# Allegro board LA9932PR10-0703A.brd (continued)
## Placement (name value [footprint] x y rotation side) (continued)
JCAM1  -  [E-T_3702K-Q08C-07L_8P]  228.21 160.88 0 bottom
JCPU1  -  [LOTES_AZIF0012-P002B_947P-T]  144.94 75.73 180 bottom
JDEG2  -  [HB_A531015-SCHR21_10P]  239.21 72.67 90 top
JDIMM1  -  [TYCO_2-2013290-1_204P]  91.44 35.35 180 bottom
JDIMM2  -  [TYCO_2-2013311-1_204P]  91.44 22.15 180 bottom
JDOCK1  -  [JAE_WD2F144WB1R300_144P]  117.84 161.25 0 bottom
JEXP1  -  [E-T_1001K-F30C-03L_30P-T]  229.69 30.09 270 top
JFAN1  -  [ACES_50273-0040N-001_4P]  47.66 89.43 0 bottom
JHDMI1  -  [CONCR_099ATAC19NBLCNF_19P]  14.44 212 0 bottom
JHP1  -  [SINGA_2SJ3082-000111F_6P-T]  290.99 165.4 270 top
JIO1  -  [E-T_1000K-Y40E-02L_40P]  1.92 176.69 270 bottom
JKB1  -  [HB_A091020-SAHR22_10P]  202.59 101 180 top
JLED1  -  [HB_A520620-SCHR22_6P]  256.17 153.79 180 top
JLOM1  -  [J-L_TNBNRBC80002008_13P-T]  250.25 207.6 0 bottom
JLVDS1  -  [ACES_59003-04006-001_40P]  221.54 170.08 0 bottom
JMDIA1  -  [HB_A520620-SCHR22_6P]  8.55 140.01 180 top
JMINI1  -  [BELLW_80003-8041_52P]  257.96 202.35 0 bottom
JMINI2  -  [BELLW_80003-8041_52P]  193.83 160.09 352.2 bottom
JMINI3  -  [BELLW_80003-1121_52P]  285.79 185.75 270 bottom
JRTC1  -  [ACES_50273-0020N-001_2P]  242.01 154.12 0 bottom
JSATA1  -  [SANTA_196003-1_22P]  81.64 61.8 90 bottom
JSATA2  -  [TYCO_2-2129116-3_31P-T]  164.01 29.82 270 bottom
JSD1  -  [ALPS_SCDACA0101_19P]  215.53 28.45 0 top
JSF1  -  [HB_A090620-SAHR21_6P]  232.34 111.2 90 top
JSIM1  -  [T-SOL_159-1000302602_10P-T]  224.09 157.48 180 top
JSPI1  -  [TYCO_2-2041070-0_20P-T]  212.06 138.5 90 top
JSPK1  -  [ACES_50273-0040N-001_4P]  179.29 9.27 0 bottom
JTAG1  -  [SHORTPADS]  198.31 86.73 0 top
JTCH1  -  [ACES_50228-0067N-001_6P]  181.56 145.11 90 bottom
JTP1  -  [HB_A520820-SCHR22_8P]  188.04 108.27 270 top
JUSB1  -  [SANTA_373130-1_9P]  281.44 207.56 0 bottom
JUSB2  -  [LOTES_ABA-USB-116-P04_9P]  291.52 191.75 90 top
JUSB3  -  [LOTES_ABA-USB-116-P04_9P]  291.52 172.75 90 top
JUSH1  -  [HB_A522020-SCHR22_20P]  40.27 94.81 0 top
JXDP1  -  [MOLEX_52435-2671_26P-T]  94.5 72.23 90 bottom
JXDP2  -  [SAMTE_BSH-030-01-L-D-A_60P]  211.88 110.38 270 bottom
L1  -  [MURAT_DLW21SN900HQ2L_0805_4P]  24.3 205.14 90 top
L2  -  [MURAT_DLW21SN900HQ2L_0805_4P]  13.64 205.14 90 top
L3  -  [MURAT_DLW21SN900HQ2L_0805_4P]  17.19 205.14 90 top
L4  -  [MURAT_DLW21SN900HQ2L_0805_4P]  20.75 205.14 90 top
L10  -  [MURAT_DLW21SN121SQ2L_4P]  230.14 165.71 270 bottom
L11  -  [MURAT_DLW21SN900SQ2L_0805_4P]  190.53 137.13 90 bottom
L13  -  [MURAT_BLM15BB221SN1D_2P]  265.52 159.71 270 top
L29  -  [TAIYO_CBC2012T4R7M_2P]  246.94 168.46 180 top
L45  -  [MURAT_BLM15BD601SN1D_2P]  179.06 24.51 270 top
L47  -  [MURAT_BLM15BD601SN1D_2P]  190.5 31.71 90 top
L51  -  [MURAT_DLW21SN900SQ2L_0805_4P]  274.87 186.78 90 top
L77  -  [MURAT_BLM15PX600SN1D_2P]  283.21 161.38 90 top
L95  -  [MURAT_DLW21SN900HQ2L_0805_4P]  277.98 187.99 90 top
L96  -  [MURAT_DLW21SN900HQ2L_0805_4P]  279.95 188.31 90 top
L99  -  [MURAT_DLW21SN900HQ2L_0805_4P]  136.76 164.11 90 top
L107  -  [MURAT_DLW21SN900SQ2L_0805_4P]  282.23 183.43 45 top
L108  -  [MURAT_DLW21SN900HQ2L_0805_4P]  285.41 188.88 90 top
L109  -  [MURAT_DLW21SN900HQ2L_0805_4P]  287.32 191.18 90 top
L110  -  [MURAT_DLW21SN900SQ2L_0805_4P]  280.65 175.78 0 top
L111  -  [MURAT_DLW21SN900HQ2L_0805_4P]  281.79 173.81 0 top
L112  -  [MURAT_DLW21SN900HQ2L_0805_4P]  281.79 171.78 0 top
L702  -  [MURAT_BLM18PG330SN1D_2P]  178.65 13.11 270 top
L703  -  [MURAT_BLM18PG330SN1D_2P]  180.13 13.11 270 top
L704  -  [MURAT_BLM18PG330SN1D_2P]  182.3 13.12 270 top
L705  -  [MURAT_BLM18PG330SN1D_2P]  183.75 13.12 270 top
L706  -  [MURAT_BLM15BD601SN1D_2P]  283.4 150.33 0 bottom
L707  -  [MURAT_BLM15BD601SN1D_2P]  283.14 159.57 0 top
LE2  -  [MURAT_DLW21SN900HQ2L_0805_4P]  191.75 13.03 0 top
LE4  -  [MURAT_DLW21SN900HQ2L_0805_4P]  191.75 15.19 0 top
LE5  -  [MURAT_DLW21SN900HQ2L_0805_4P]  194.89 31.07 0 top
LED1  -  [LED_LTW-193ZDS5_2P]  277.14 200.7 270 top
LH1  -  [MURAT_BLM18PG181SN1D_2P]  169.05 151.3 0 top
LV16  -  [R_0402]  70.92 148.33 0 top
LV17  -  [R_0402]  58.13 130.03 180 top
LV18  -  [R_0402]  57.22 128.25 90 top
LV19  -  [R_0402]  77.48 141.47 180 top
LV21  -  [R_0402]  58.56 126.74 180 top
LV30  -  [R_0402]  64.12 142.99 0 top
ME1  -  [SHORTPADS]  180.41 129.91 180 top
NOREF  -  []  167.59 15.85 0 top
NOREF#2  -  []  119.48 47.33 0 top
NOREF#3  -  []  3.89 193.15 0 top
NOREF#4  -  []  90.19 137.15 0 top
NOREF#5  -  []  183.39 167.72 0 top
NOREF#6  -  []  250.59 86.75 0 top
NOREF#7  -  []  94.24 42.28 0 top
NOREF#8  -  []  3.89 169.85 0 top
NOREF#9  -  []  257.71 161.85 0 top
NOREF#10  -  []  142.18 118.1 90 top
NOREF#11  -  []  293.49 208.3 0 top
NOREF#12  -  []  115.19 41.83 0 top
NOREF#13  -  []  16.45 270.94 0 top
NOREF#14  -  []  49.34 146.2 0 top
NOREF#15  -  []  227.79 44.15 0 top
NOREF#16  -  []  165.36 -33.98 0 top
NOREF#17  -  []  152.65 76 0 top
NOREF#18  -  []  152.65 105.7 0 top
NOREF#19  -  []  102.15 76 0 top
NOREF#20  -  []  234.59 150.85 0 top
NOREF#21  -  []  102.15 105.7 0 top
NOREF#22  -  []  227.79 23.15 0 top
NOREF#23  -  []  59.79 117.05 0 top
NOREF#24  -  []  89.79 167.72 0 top
NOREF#25  -  []  226.25 60.63 180 bottom
NOREF#26  -  []  216.06 22.88 180 bottom
NOREF#27  -  []  44.03 50.04 180 bottom
NOREF#28  -  []  217.81 18.08 180 bottom
PBATT1  -  [OCTEK_BTJ-09WKFB_9P]  60.79 169.75 0 bottom
PC3  -  [C_0603]  241.37 152.07 0 top
PC5  -  [C_0402]  80.89 166.8 0 top
PC8  -  [C_0805]  10.03 175.97 270 top
PC12  -  [C_0603]  22.54 178.55 0 bottom
PC13  -  [C_0805]  9.91 171.15 270 top
PC14  -  [C_0603]  9.97 172.28 270 bottom
PC17  -  [C_0402]  166.96 167.5 180 top
PC101  -  [C_APXK6R3ARA221MF451]  219.58 46.69 270 top
PC102  -  [C_APXK6R3ARA221MF451]  214.01 55.5 180 top
PC103  -  [C_0402]  205.45 51.41 0 top
PC105  -  [C_0402]  203.27 37.4 270 top
PC106  -  [C_0402]  201.35 48.17 270 top
PC109  -  [C_0805]  202.66 48.59 270 top
PC110  -  [C_0805]  205.04 40.07 270 top
PC111  -  [C_0603]  198.31 43.11 270 top
PC112  -  [C_0603]  198.4 34.41 270 top
PC114  -  [C_0603]  193.3 38.09 0 top
PC116  -  [C_0603]  208.03 33.14 180 top
PC117  -  [C_0603]  202.19 37.33 270 top
PC118  -  [C_0603]  202.19 38.34 90 top
PC119  -  [C_0603]  207.35 42.65 180 top
PC120  -  [C_0603]  194.96 42.23 180 top
PC201  -  [C_APXK2R5ARA331MF451]  160.21 75.3 180 bottom
PC202  -  [C_0805]  169.99 87.39 270 top
PC203  -  [C_0805]  168.15 87.39 270 top
PC205  -  [C_0402]  166.37 92.99 90 top
PC206  -  [C_0603]  174.25 89.84 180 top
PC207  -  [C_0805]  172.68 82.03 180 top
PC208  -  [C_0805]  172.68 83.75 180 top
PC209  -  [C_0402]  177.23 83.25 270 top
PC210  -  [C_0603]  180.53 90.99 0 top
PC211  -  [C_0402]  180.28 83.12 270 top
PC212  -  [C_0603]  161.1 80.83 0 top
PC213  -  [C_0603]  178.25 89.72 90 top
PC214  -  [C_0402]  178.5 82.21 90 top
PC215  -  [C_0402]  180.52 86.67 0 top
PC216  -  [C_SX]  154.18 82.14 90 bottom
PC301  -  [C_APXK2R5ARA331MF451]  158.75 102.99 180 bottom
PC302  -  [C_0402]  169.76 96.94 90 top
PC303  -  [C_0402]  167.32 94.81 270 top
PC304  -  [C_0805]  168.47 96.93 90 top
PC305  -  [C_0805]  166.75 96.93 90 top
PC306  -  [C_0603]  172.47 95.49 270 top
PC307  -  [C_0402]  179.31 95.75 0 top
PC308  -  [C_0603]  173.93 98.48 0 top
PC309  -  [C_0603]  162.18 100.96 90 top
PC310  -  [C_0805]  163.6 105.45 0 top
PC400  -  [C_0603]  203.2 58.54 180 top
PC401  -  [C_0402]  203.15 57.46 180 top
PC402  -  [C_0402]  205.37 55.11 180 top
PC403  -  [C_0603]  194.88 59.74 180 top
PC404  -  [C_0603]  194.88 58.47 180 top
PC405  -  [C_0402]  194.71 60.82 180 top
PC406  -  [C_0402]  200.22 52.9 270 top
PC407  -  [C_0402]  198.82 58.33 90 top
PC500  -  [C_0402]  124.72 148.59 270 bottom
PC509  -  [C_0603]  124.4 138.17 90 bottom
PC510  -  [C_0402]  126.57 149.47 180 bottom
PC511  -  [C_0603]  128.02 139.56 270 bottom
PC512  -  [C_0805]  117.77 135.94 0 top
PC513  -  [C_0805]  117.77 135.94 0 bottom
PC514  -  [C_0805]  117.77 137.72 0 bottom
PC515  -  [C_0402]  118.04 139.06 0 bottom
PC516  -  [C_0402]  98.87 152.91 270 bottom
PC518  -  [C_0402]  127.61 140.92 180 top
PC520  -  [C_0402]  129.8 145.9 90 top
PC521  -  [C_0402]  131.95 143.61 90 bottom
PC522  -  [C_0603]  119.57 141.53 0 bottom
PC524  -  [C_0603]  115 129.28 0 top
PC525  -  [C_0402]  125.99 144.95 90 top
PC526  -  [C_0402]  125.1 144.95 90 top
PC527  -  [C_0402]  126.87 144.95 90 top
PC528  -  [C_0402]  129.16 142.56 270 bottom
PC529  -  [C_0603]  132.4 141.47 180 bottom
PC530  -  [C_EEEFK1E101YP]  115.24 144.07 90 bottom
PC531  -  [C_EEEFK1E101YP]  108.13 144.03 90 bottom
PC532  -  [C_EEEFK1E101YP]  100.89 144.03 90 bottom
PC533  -  [C_0805]  129.19 134.29 180 top
PC534  -  [C_0805]  129.19 132.58 180 bottom
PC535  -  [C_0805]  129.19 134.29 180 bottom
PC536  -  [C_0402]  128.92 135.63 180 bottom
PC538  -  [C_0603]  132.4 140.26 180 bottom
PC539  -  [C_0402]  130.06 143.63 180 bottom
PC540  -  [C_0402]  130.06 144.52 180 bottom
PC541  -  [C_0402]  126.23 143.69 0 top
PC542  -  [C_0603]  125.6 138.17 90 bottom
PC543  -  [C_0603]  128.84 128.26 180 top
PC545  -  [C_0402]  129.29 143.64 270 top
PC546  -  [C_0402]  126.23 142.8 0 top
PC547  -  [C_0402]  128.67 145.02 180 top
PC548  -  [C_0402]  119.25 145.27 90 bottom
PC600  -  [C_0402]  17.12 143.8 90 top
PC601  -  [C_0603]  13.15 157.03 90 top
PC602  -  [C_0402]  4.5 162.17 0 bottom
PC603  -  [C_0805]  14.67 156.94 90 top
PC604  -  [C_0805]  14.67 156.94 90 bottom
PC605  -  [C_0603]  20.96 154.49 270 top
PC606  -  [C_D2]  50.14 153.91 0 top
PC607  -  [C_0603]  9.78 164.84 180 bottom
PC608  -  [C_0603]  24.39 154.87 270 top
PC610  -  [C_0603]  22.23 154.87 270 top
PC611  -  [C_0402]  24.13 144.15 270 top
PC612  -  [C_0402]  25.91 140.57 90 top
PC613  -  [C_0402]  24.14 142.36 180 top
PC614  -  [C_0402]  25.02 143.26 270 top
PC615  -  [C_0402]  25.91 144.15 270 top
PC616  -  [C_0402]  26.86 144.15 270 top
PC617  -  [C_0603]  27.88 149.02 0 top
PC618  -  [C_0603]  27.88 150.23 0 top
PC619  -  [C_0603]  16.51 157.66 0 top
PC621  -  [C_0805]  16.36 156.07 0 top
PC622  -  [C_0805]  16.36 156.07 0 bottom
PC623  -  [C_0603]  26.93 153.85 180 top
PC624  -  [C_0402]  27.8 144.77 0 top
PC626  -  [C_0603]  29.78 147.75 270 top
PC627  -  [C_0402]  30.86 147.64 270 top
PC628  -  [C_D2]  38.93 159.53 270 bottom
PC629  -  [C_D2]  51.65 127.82 180 top
PC630  -  [C_0402]  28.72 145.66 180 top
PC631  -  [C_0603]  23.88 156.96 270 bottom
PC632  -  [C_0402]  29.97 145.42 270 top
PC660  -  [C_0603]  104.9 131.63 90 bottom
PC661  -  [C_0603]  104.33 139.69 90 bottom
PC662  -  [C_0603]  104.33 139.69 90 top
PC663  -  [C_0603]  104.33 138.17 270 top
PC664  -  [C_0603]  104.33 138.17 270 bottom
PC665  -  [C_0402]  108.52 133.54 270 top
PC666  -  [C_0402]  108.02 130.79 90 top
PC667  -  [C_0402]  104.92 135.12 180 bottom
PC668  -  [C_0402]  107.24 128.32 0 bottom
PC669  -  [C_0603]  106.94 123.88 270 bottom
PC670  -  [C_0603]  108.14 123.88 270 bottom
PC672  -  [C_0603]  99.06 128.26 0 bottom
PC674  -  [C_0402]  99.24 129.34 0 bottom
PC675  -  [C_0402]  106.16 121.47 0 bottom
PC677  -  [C_D2]  49.81 132.64 180 top
PC680  -  [C_0603]  103.7 131.63 90 bottom
PC700  -  [C_0603]  25.6 170.09 0 top
PC703  -  [C_0603]  51.88 164.57 90 bottom
PC704  -  [C_0402]  52.31 166.87 0 top
PC705  -  [C_0402]  52.96 165.42 270 bottom
PC706  -  [C_0603]  56.01 160.65 0 top
PC707  -  [C_0805]  55.18 166.21 90 top
PC708  -  [C_0402]  50.43 163.82 180 bottom
PC709  -  [C_0603]  56.77 164.96 180 top
PC710  -  [C_0402]  57.35 159.44 180 bottom
PC712  -  [C_0805]  64.26 152.64 180 bottom
PC713  -  [C_0805]  64.26 154.36 180 bottom
PC714  -  [C_0805]  58.13 158.04 180 bottom
PC715  -  [C_0603]  67.06 154.3 180 top
PC716  -  [C_0402]  50.43 162.93 180 bottom
PC717  -  [C_0603]  87.34 154.12 270 bottom
PC718  -  [C_0805]  88.84 154.26 270 bottom
PC719  -  [C_0805]  90.62 154.26 270 bottom
PC720  -  [C_0603]  45.47 168.58 270 bottom
PC721  -  [C_0402]  51.75 159.96 270 bottom
PC722  -  [C_0402]  51.77 158.11 180 bottom
PC723  -  [C_0402]  50.87 159.04 90 bottom
PC724  -  [C_0805]  59.88 167.21 270 top
PC725  -  [C_0402]  221.44 141.15 180 top
PC726  -  [C_0402]  229.81 140.4 270 top
PC727  -  [C_0402]  231.99 145.11 180 top
PC728  -  [C_0805]  61.6 167.21 270 top
PC729  -  [C_0402]  223.08 147.36 90 top
PC730  -  [C_0402]  221.5 145.79 180 top
PC731  -  [C_0805]  81.89 154.46 270 bottom
PC732  -  [C_0805]  83.67 154.46 270 bottom
PC733  -  [C_0402]  232.65 138.1 0 top
PC734  -  [C_0805]  58.13 156.33 180 bottom
PC735  -  [C_0603]  63.27 152.31 180 top
PC736  -  [C_0402]  230.9 141.56 270 top
PC737  -  [C_0805]  83.28 163.6 180 top
PC738  -  [C_0805]  83.28 161.79 180 top
PC739  -  [C_0805]  83.28 165.38 180 top
PC801  -  [C_0402]  233.49 82.91 90 top
PC805  -  [C_0402]  227.98 87.75 180 top
PC807  -  [C_0805]  99.51 169.83 90 top
PC808  -  [C_0402]  193.11 46.36 270 top
PC809  -  [C_0402]  101.79 163.52 270 top
PC810  -  [C_0402]  192.09 46.36 270 top
PC811  -  [C_0603]  72.65 152.29 270 top
PC812  -  [C_0402]  184.85 45.57 90 top
PC813  -  [C_0603]  35.56 138.99 270 top
PC814  -  [C_0402]  176 16.96 90 top
PC815  -  [C_0603]  37.21 137.15 270 top
PC816  -  [C_0603]  43.82 137.47 270 top
PC817  -  [C_0402]  44.9 137.54 270 top
PC818  -  [C_0603]  41.72 137.18 270 top
PC819  -  [C_0603]  46.04 140.13 270 top
PC820  -  [C_0603]  35.5 140.13 180 top
PC900  -  [C_0805]  118.05 97.55 270 bottom
PC901  -  [C_0805]  119.95 97.55 270 bottom
PC902  -  [C_0805]  121.86 97.55 270 bottom
PC903  -  [C_0805]  123.76 97.55 270 bottom
PC904  -  [C_0805]  125.67 97.55 270 bottom
PC905  -  [C_D1]  130.61 116.2 0 bottom
PC906  -  [C_D1]  120.39 120.32 0 bottom
PC907  -  [C_D1]  124.58 92.76 0 top
PC908  -  [C_D1]  126.36 120.32 0 top
PC909  -  [C_0805]  127.57 97.55 270 bottom
PC910  -  [C_0805]  129.48 97.55 270 bottom
PC911  -  [C_0805]  131.38 97.55 270 bottom
PC912  -  [C_0805]  133.29 97.55 270 bottom
PC913  -  [C_0805]  135.19 97.55 270 bottom
PC914  -  [C_0805]  137.1 97.55 270 bottom
PC916  -  [C_D1]  120.47 120.2 180 top
PC917  -  [C_0805]  116.84 114.65 90 bottom
PC918  -  [C_0805]  120.46 114.65 90 bottom
PC919  -  [C_0805]  123.83 114.65 90 bottom
PC920  -  [C_0805]  127.51 114.65 90 bottom
PC921  -  [C_0805]  118.05 97.55 270 top
PC922  -  [C_0805]  137.1 97.55 270 top
PC923  -  [C_0805]  135.19 97.55 270 top
PC924  -  [C_0805]  133.29 97.55 270 top
PC925  -  [C_0805]  131.38 97.55 270 top
PC926  -  [C_0805]  129.48 97.55 270 top
PC927  -  [C_0402]  68 135.44 0 top
PC928  -  [C_0402]  71.87 133.98 0 top
PC929  -  [C_0402]  70.94 132.81 180 top
PC930  -  [C_0402]  73.78 135.44 0 top
PC931  -  [C_0402]  68.91 132.83 180 top
PC932  -  [C_0402]  68 131.63 0 top
PC933  -  [C_0402]  68 133.98 0 top
PC934  -  [C_0402]  71.87 135.44 0 top
PC935  -  [C_0805]  127.57 97.55 270 top
PC936  -  [C_0805]  125.67 97.55 270 top
PC937  -  [C_0805]  123.76 97.55 270 top
PC938  -  [C_0805]  121.86 97.55 270 top
PC939  -  [C_0805]  119.95 97.55 270 top
PC940  -  [C_0805]  127.51 114.65 90 top
PC941  -  [C_0805]  123.83 114.65 90 top
PC942  -  [C_0805]  120.46 114.65 90 top
PC943  -  [C_0805]  116.84 114.65 90 top
PC944  -  [C_0402]  73.84 133.98 0 top
PC945  -  [C_0402]  71.81 131.63 0 top
PC946  -  [C_0402]  69.97 133.98 0 top
PC947  -  [C_0402]  72.79 132.81 180 top
PC948  -  [C_0402]  73.84 131.63 0 top
PC949  -  [C_0402]  74.75 132.83 180 top
PC950  -  [C_0402]  70.03 131.63 0 top
PC951  -  [C_0402]  74.69 136.58 180 top
PC963  -  [C_0805]  56.22 139.75 180 bottom
PC964  -  [C_0805]  56.22 138.04 180 bottom
PC965  -  [C_0805]  56.22 141.47 180 bottom
PC966  -  [C_0805]  56.22 143.18 180 bottom
PC970  -  [C_0805]  56.22 144.9 180 bottom
PC971  -  [C_0805]  56.22 146.61 180 bottom
PC972  -  [C_0805]  56.22 148.33 180 bottom
PD2  -  [TVNST52302AB0_SOT523-3]  74.58 165.81 270 top
PD3  -  [BAS40-05W_SC70-3]  240.41 152.67 180 top
PD4  -  [TVNST52302AB0_SOT523-3]  71.87 165.81 270 top
PD7  -  [SDMK0340L-7-F_SOD323-2]  166.44 163.87 0 top
PD700  -  [SBR3A40SA-13_SMA2]  22.13 170.81 180 top
PD701  -  [RB717F_SOT323-3]  46.16 167.38 90 top
PD702  -  [RB751V-40_SOD323-2]  57.84 162.17 180 top
PD800  -  [PDS5100H-13_POWERDI5-3]  95.06 159.88 180 top
PD806  -  [PDS5100H-13_POWERDI5-3]  85.11 158.57 180 top
PD807  -  [SDMK0340L-7-F_SOD323-2]  171.52 75.94 90 top
PD808  -  [PDS5100H-13_POWERDI5-3]  103.06 165.53 0 bottom
PD810  -  [RB717F_SOT323-3]  186.19 47.87 270 top
PD811  -  [SDMK0340L-7-F_SOD323-2]  111.44 156.14 90 top
PD813  -  [RB717F_SOT323-3]  179.9 39.42 270 top
PD815  -  [RB717F_SOT323-3]  171.78 22 270 top
PD818  -  [SDMK0340L-7-F_SOD323-2]  225.94 75.49 0 top
PD819  -  [SDMK0340L-7-F_SOD323-2]  186.25 50.3 90 top
PD820  -  [SDMK0340L-7-F_SOD323-2]  175.2 22.26 90 top
PD821  -  [SDMK0340L-7-F_SOD323-2]  179.81 16.87 180 top
PH500  -  [R_0402]  135.83 133.23 270 bottom
PH501  -  [R_0402]  136.72 123.95 270 bottom
PH600  -  [R_0402]  14.1 160.72 270 bottom
PH601  -  [R_0402]  28.84 155.63 180 bottom
PJP1  -  [JUMP_43X118]  24.58 182.38 90 bottom
PJP2  -  [JUMP_43X39]  25.73 201.67 180 top
PJP3  -  [JUMP_43X79]  80.54 39.74 0 top
PJP4  -  [JUMP_43X79]  174.2 48.25 0 top
PJP53  -  [JUMP_43X39]  89.92 55.12 270 top
PJP60  -  [JUMP_43X79]  264.63 157.28 0 bottom
PJP61  -  [JUMP_43X39]  209.68 119.51 270 top
PJP62  -  [JUMP_43X39]  274.63 156.07 180 bottom
PJP63  -  [JUMP_43X39]  183.45 78.78 90 top
PJP64  -  [JUMP_43X39]  78.73 46.66 0 top
PJP65  -  [JUMP_43X39]  220.87 68.57 180 top
PJP67  -  [JUMP_43X39]  191.76 167.57 0 top
PJP100  -  [JUMP_43X79]  217.36 51.78 270 top
PJP101  -  [JUMP_43X118]  218.21 61.78 0 top
PJP102  -  [JUMP_43X118]  221.87 50.68 90 top
PJP103  -  [JUMP_43X118]  218.21 56.51 0 top
PJP200  -  [JUMP_43X118]  169.74 90.56 90 top
PJP201  -  [JUMP_43X39]  171.82 85.72 0 top
PJP202  -  [JUMP_43X39]  174.89 82.29 180 top
PJP203  -  [JUMP_43X118]  152.29 57.55 45 top
PJP204  -  [JUMP_43X118]  148.61 61.23 45 top
PJP300  -  [JUMP_43X79]  169.67 94.12 90 top
PJP301  -  [JUMP_43X118]  160.34 105.7 270 top
PJP400  -  [JUMP_43X79]  204.87 57.65 0 top
PJP401  -  [JUMP_43X79]  197.36 62.01 270 top
PJP500  -  [JUMP_43X118]  100.08 156.22 90 bottom
PJP600  -  [JUMP_43X118]  3.96 158.87 0 bottom
PJP602  -  [JUMP_43X39]  28.64 143.32 270 top
PJP609  -  [JUMP_43X79]  103.82 130.02 270 bottom
PJP610  -  [JUMP_43X79]  101.5 139.18 0 bottom
PJP611  -  [JUMP_43X79]  107.51 126.65 270 bottom
PJP612  -  [JUMP_43X79]  95.78 125.78 0 bottom
PJP700  -  [JUMP_43X118]  60.01 163.48 270 bottom
PJP701  -  [JUMP_43X39]  49.21 161.74 270 bottom
PJP702  -  [JUMP_43X79]  295.42 185.14 90 top
PJPDC1  -  [JESS_UCNR2451M005-0_5P]  16.96 178.65 90 bottom
PL2  -  [TAIYO_FBMJ4516HS720NT_2P]  76.53 165.49 270 top
PL3  -  [TAIYO_FBMJ4516HS720NT_2P]  79.02 165.49 270 top
PL4  -  [MURAT_BLM15AG102SN1D_2P]  12.1 182.28 90 bottom
PL5  -  [KC_FBMA-L18-453215_L1812_2P]  11.24 177.91 270 bottom
PL101  -  [CYNTE_PCMB063T-2R2MS_2P]  218.22 36.34 180 top
PL102  -  [CYNTE_PCMB063T-3R3MS_2P]  212 43.32 90 top
PL103  -  [CYNTE_PCMB053T-1R0MS_2P]  198.32 49.79 270 top
PL201  -  [TOKO_FDUE1040D-1R0M-P3_2P]  161.93 81.65 90 bottom
PL301  -  [TOKO_FDSD0630-H-1R0M-P3_2P]  164.66 95.81 180 bottom
PL401  -  [CYNTE_PH041H-1R0MS_2P]  197.7 55.11 180 top
PL502  -  [NEC_MPC0740LR42C_2P]  114.37 121.29 90 bottom
PL503  -  [NEC_MPC0740LR42C_2P]  132.65 121.29 90 bottom
PL504  -  [L_1812-1806]  100.08 154.76 90 bottom
PL600  -  [NEC_MPC0740LR42C_2P]  19.74 166.49 180 bottom
PL601  -  [NEC_MPC0740LR42C_2P]  31.3 159.63 180 bottom
PL602  -  [L_1812-1806]  6.52 158.87 180 bottom
PL603  -  [TOKO_FDSD0420-H-1R0M-P3T_2P]  107.38 136.92 90 bottom
PL700  -  [TOKO_FDVE1040-H-5R6M-P3_2P]  82.18 160.48 180 bottom
PL701  -  [CYNTE_PCMB053T-1R0MS_2P]  60.01 160.88 90 bottom
PQ1  -  [FDV301N_NL_SOT23-3]  216.79 124.03 180 top
PQ2  -  [MMST3904-7-F_SOT323-3]  218.95 119.43 90 top
PQ4  -  [FDS6679AZ_SO8]  15.62 176.37 180 top
PQ6  -  [IMD2AT-108_SC74-6]  9.98 179.25 90 top
PQ7  -  [FDN338P_NL_SOT23-3]  167.45 171.47 180 top
PQ101  -  [SIS412DN-T1-GE3_POWERPAK8-5]  209.65 38.62 90 top
PQ102  -  [SIS412DN-T1-GE3_POWERPAK8-5]  207.11 48.15 90 top
PQ103  -  [SI7716ADN-T1-GE3_POWERPAK8-5]  206.78 36.67 270 top
PQ104  -  [SI7716ADN-T1-GE3_POWERPAK8-5]  204.24 46.19 270 top
PQ201  -  [SIR472DP-T1-GE3_POWERPAK8-5]  160.91 91.73 270 top
PQ203  -  [SIR818DP-T1_POWERPAK-SO8-5]  166.25 82.54 90 top
PQ301  -  [SIS412DN-T1-GE3_POWERPAK8-5]  162.27 95.6 270 top
PQ303  -  [SI7716ADN-T1-GE3_POWERPAK8-5]  165.2 97.49 90 top
PQ505  -  [SIR472DP-T1-GE3_POWERPAK8-5]  116.33 130.48 180 bottom
PQ508  -  [SI7170DP-T1-GE3_POWERPAK8-5]  118.81 130.23 0 bottom
PQ509  -  [SIR472DP-T1-GE3_POWERPAK8-5]  134.43 130.48 180 bottom
PQ512  -  [SI7170DP-T1-GE3_POWERPAK8-5]  124.4 130.23 0 bottom
PQ600  -  [CSD86350Q5D_SON8]  12.05 156.81 180 bottom
PQ601  -  [CSD86350Q5D_SON8]  16.42 158.63 90 bottom
PQ610  -  [SSM3K7002FU_SC70-3]  102.11 119.5 270 bottom
PQ700  -  [SI4835BDY-T1-E3_SO8]  23.03 173.35 90 top
PQ701  -  [NTR4502PT1G_SOT23-3]  37.66 168.67 180 top
PQ702  -  [NTR4502PT1G_SOT23-3]  33.59 168.67 180 top
PQ703  -  [NTGD4161PT1G_TSOP6]  147.42 166.48 270 top
PQ704  -  [SIR472DP-T1-GE3_POWERPAK8-5]  68.9 165.6 270 bottom
PQ705  -  [SIR472DP-T1-GE3_POWERPAK8-5]  68.9 160.01 270 bottom
PQ706  -  [SIR472DP-T1-GE3_POWERPAK8-5]  63.43 159.88 270 top
PQ707  -  [2N7002DW-T-R7_SOT363-6]  234.22 144.15 270 top
PQ709  -  [RHU002N06_SOT323-3]  223.29 138.34 0 top
PQ710  -  [RHU002N06_SOT323-3]  237.36 138.83 0 top
PQ711  -  [SIR472DP-T1-GE3_POWERPAK8-5]  63.43 165.6 270 top
PQ800  -  [SI4835BDY-T1-E3_SO8]  97.47 156.62 180 top
PQ801  -  [FDN338P_NL_SOT23-3]  168.53 76.28 180 top
PQ802  -  [RHU002N06_SOT323-3]  226.25 82.5 0 top
PQ805  -  [2N7002DW-T-R7_SOT363-6]  226.02 78.43 270 top
PQ806  -  [2N7002DW-T-R7_SOT363-6]  230.34 80.97 270 top
PQ807  -  [2N7002DW-T-R7_SOT363-6]  172.87 73.16 270 top
PQ809  -  [SI4835BDY-T1-E3_SO8]  85.51 151.5 90 top
PQ810  -  [FDS6679AZ_SO8]  101.31 168.58 90 bottom
PQ811  -  [FDS6679AZ_SO8]  77.97 158.59 180 top
PQ812  -  [2N7002DW-T-R7_SOT363-6]  112.13 151.85 0 top
PQ813  -  [2N7002DW-T-R7_SOT363-6]  187.1 39.76 270 top
PQ814  -  [FDN338P_NL_SOT23-3]  181.08 36.19 270 top
PQ815  -  [FDS6679AZ_SO8]  106.87 161.95 180 top
PQ816  -  [FDV301N_NL_SOT23-3]  98.87 163.03 0 top
PQ817  -  [RHU002N06_SOT323-3]  188.47 51.78 180 top
PQ818  -  [RHU002N06_SOT323-3]  179.01 45.74 0 top
PQ819  -  [2N7002DW-T-R7_SOT363-6]  182.92 49.19 90 top
PQ821  -  [2N7002DW-T-R7_SOT363-6]  188.82 41.12 90 top
PQ822  -  [FDN338P_NL_SOT23-3]  181.21 42.66 270 top
PQ823  -  [FDN338P_NL_SOT23-3]  214.64 94.29 270 top
PQ824  -  [2N7002DW-T-R7_SOT363-6]  220.52 93.36 0 top
PQ825  -  [RHU002N06_SOT323-3]  194.95 81.63 180 top
PQ826  -  [FDS6679AZ_SO8]  103.47 167.88 270 top
PQ827  -  [RHU002N06_SOT323-3]  184.75 39.42 90 top
PQ828  -  [FDN338P_NL_SOT23-3]  168.15 22.16 0 top
PQ829  -  [RHU002N06_SOT323-3]  170.77 24.67 270 top
PQ830  -  [FDN338P_NL_SOT23-3]  176.15 14.49 90 top
PQ831  -  [RHU002N06_SOT323-3]  174.55 18.89 90 top
PR1  -  [R_0402]  242.13 153.65 90 top
PR6  -  [R_0402]  163.31 161.71 0 top
PR10  -  [R_0402]  219.27 123.89 270 top
PR11  -  [R_0402]  220.14 124.77 0 top
PR12  -  [R_0402]  220.16 122.98 90 top
PR13  -  [R_0402]  214.31 122.85 90 top
PR14  -  [R_0402]  221.18 119.12 180 top
PR15  -  [R_0402]  214.25 121.01 90 top
PR16  -  [R_0402]  220.27 120.07 0 top
PR18  -  [R_0402]  8.7 174.28 90 top
PR20  -  [R_0402]  10.36 172.27 180 top
PR22  -  [R_0805]  11.5 172.42 270 bottom
PR23  -  [R_0402]  7.81 175.2 270 top
PR25  -  [R_0402]  8.71 176.08 180 top
PR26  -  [R0402_0OHM]  168.8 167.5 180 top
PR100  -  [R_0402]  193.79 36.11 0 top
PR101  -  [R_0402]  193.79 39.23 0 top
PR102  -  [R_0402]  193.79 35.17 0 top
PR103  -  [R0402_0OHM]  194.71 37 180 top
PR104  -  [R_0402]  193.79 40.12 0 top
PR105  -  [R_0402]  194.71 34.28 180 top
PR106  -  [R_0402]  194.71 41.01 180 top
PR107  -  [R_0603]  199.53 41.71 90 top
PR108  -  [R_0603]  199.67 33.01 90 top
PR109  -  [R_1206]  204.92 33.2 90 top
PR110  -  [R0402_0OHM]  196.36 42.6 270 top
PR111  -  [R_0402]  197.25 42.6 270 top
PR112  -  [R_1206]  204.6 42.34 180 top
PR118  -  [R0402_0OHM]  196.37 33.51 90 top
PR119  -  [R_0402]  197.26 34.42 270 top
PR200  -  [R_0603]  172.91 88.7 270 top
PR201  -  [R_0402]  176.28 90.62 270 top
PR202  -  [R_1206]  163.7 80.44 0 top
PR203  -  [R_0603]  179.45 91.11 270 top
PR204  -  [R_0402]  179.39 83.12 270 top
PR205  -  [R_0402]  181.37 88.64 180 top
PR206  -  [R_0402]  181.37 87.75 180 top
PR207  -  [R_0402]  181.43 84 180 top
PR208  -  [R0402_0OHM]  181.43 84.89 180 top
PR209  -  [R_0402]  181.37 89.53 180 top
PR210  -  [R0402_0OHM]  181.43 85.78 180 top
PR211  -  [R0402_0OHM]  177.17 90.62 270 top
PR300  -  [R_0402]  178.18 93.09 270 top
PR301  -  [R_0603]  174.44 92.95 180 top
PR302  -  [R_0402]  179.07 92.18 90 top
PR303  -  [R_0402]  180.23 93.97 180 top
PR304  -  [R_1206]  163.64 101.46 0 top
PR305  -  [R_0402]  177.81 98.29 180 top
PR306  -  [R_0402]  180.23 97.53 180 top
PR307  -  [R_0402]  180.23 96.64 180 top
PR308  -  [R0402_0OHM]  180.23 94.86 180 top
PR309  -  [R0402_0OHM]  173.12 96.57 180 top
PR401  -  [R_0805]  200.34 59.26 270 top
PR402  -  [R_0402]  205.37 54.22 180 top
PR403  -  [R_0402]  202 51.98 90 top
PR405  -  [R_0402]  204.46 53.33 0 top
PR406  -  [R0402_0OHM]  201.11 51.98 90 top
PR500  -  [R_0402]  121.03 146.5 180 bottom
PR503  -  [R_0402]  121.03 147.39 180 bottom
PR504  -  [R_0402]  121.03 148.28 180 bottom
PR507  -  [R_0402]  119.88 143.82 0 bottom
PR509  -  [R_0402]  120.12 144.71 0 bottom
PR511  -  [R0402_0OHM]  122.75 148.59 270 bottom
PR512  -  [R_0402]  120.12 145.6 0 bottom
PR519  -  [R_0402]  123.83 147.68 90 bottom
PR520  -  [R0402_0OHM]  123.33 139.56 180 bottom
PR521  -  [R_0402]  125.6 147.68 90 bottom
PR524  -  [R0402_0OHM]  126.49 148.59 270 bottom
PR525  -  [R_0402]  127.38 148.59 270 bottom
PR526  -  [R0402_0OHM]  129.1 139.58 270 bottom
PR528  -  [R_0402]  128.27 148.59 270 bottom
PR529  -  [R_0402]  128.91 146.81 270 bottom
PR530  -  [R_0402]  128.77 141.85 0 top
PR533  -  [R_0402]  128.92 147.69 180 top
PR534  -  [R_0603]  119.57 142.74 0 bottom
PR535  -  [R_0402]  131 144.53 270 bottom
PR536  -  [R_0603]  133.61 138.99 270 bottom
PR537  -  [R_0402]  128.91 145.9 90 top
PR538  -  [R_0603]  133.61 137.59 90 top
PR539  -  [R_0402]  125.08 146.74 0 top
PR541  -  [R_1206]  116.46 130.67 90 top
PR543  -  [R_0402]  128.02 145.9 90 top
PR544  -  [R_0402]  134.69 138.15 90 bottom
PR545  -  [R_0402]  130.99 145.41 0 bottom
PR546  -  [R_0402]  134.69 139.07 270 top
PR548  -  [R0402_0OHM]  130.93 142.55 0 bottom
PR549  -  [R_0402]  130.05 142.56 270 bottom
PR550  -  [R_0603]  126.81 138.17 90 bottom
PR551  -  [R_0402]  130.05 139.87 90 bottom
PR552  -  [R_0603]  132.4 138.99 270 bottom
PR553  -  [R_0603]  132.4 137.59 90 top
PR554  -  [R_1206]  127.89 130.1 90 top
PR555  -  [R_0402]  131.32 139.07 270 top
PR556  -  [R_0402]  131.26 138.09 90 bottom
PR558  -  [R_0402]  127.14 141.89 180 top
PR600  -  [R0402_0OHM]  15.36 144.71 0 top
PR602  -  [R_0402]  18.18 146.83 180 top
PR604  -  [R_0402]  18.18 147.89 180 top
PR605  -  [R_0402]  17.26 148.96 0 top
PR607  -  [R_0402]  15.36 143.82 0 top
PR608  -  [R_0402]  18.18 150.1 180 top
PR610  -  [R_0402]  17.26 151.56 0 top
PR612  -  [R_0402]  17.26 152.45 0 top
PR614  -  [R_0603]  19.75 153.09 90 top
PR615  -  [R_0402]  17.91 145.95 180 top
PR616  -  [R_0402]  18.01 143.8 90 top
PR618  -  [R0402_0OHM]  15.95 148.96 180 top
PR619  -  [R_0402]  33.21 150.62 270 top
PR620  -  [R0402_0OHM]  15.95 147.89 180 top
PR621  -  [R0402_0OHM]  15.95 150.1 180 top
PR622  -  [R_1206]  6.86 164.84 270 bottom
PR623  -  [R_0402]  34.16 150.62 270 top
PR624  -  [R_0402]  35.05 150.62 270 top
PR625  -  [R0402_0OHM]  15.95 151.56 180 top
PR626  -  [R_0402]  36.01 149.71 90 top
PR627  -  [R_0402]  19.81 143.8 90 top
PR628  -  [R0402_0OHM]  15.95 152.45 180 top
PR629  -  [R0402_0OHM]  18.92 143.8 90 top
PR631  -  [R_0402]  21.59 143.33 90 top
PR632  -  [R_0402]  21.6 141.47 180 top
PR633  -  [R_0402]  21.6 140.58 180 top
PR634  -  [R_0402]  20.97 142.42 180 top
PR635  -  [R0402_0OHM]  23.31 153.99 90 top
PR638  -  [R_0402]  23.24 144.15 270 top
PR639  -  [R_0402]  24.12 140.58 0 top
PR640  -  [R_0402]  26.8 140.57 90 top
PR642  -  [R_0402]  25.03 141.47 180 top
PR643  -  [R0402_0OHM]  30.32 150.06 0 top
PR644  -  [R_0402]  23.24 141.48 270 top
PR645  -  [R_0402]  30.32 149.17 0 top
PR648  -  [R_0402]  31.75 147.64 270 top
PR649  -  [R_0603]  27.43 151.31 90 top
PR650  -  [R0402_0OHM]  48.46 135.56 180 top
PR651  -  [R_0402]  30.1 153.61 270 top
PR652  -  [R_0402]  31.05 153.61 270 top
PR653  -  [R_1206]  22.48 156.01 180 bottom
PR654  -  [R_0402]  32.01 153.61 270 top
PR655  -  [R_0402]  27.8 147.44 0 top
PR656  -  [R_0402]  32.96 152.69 90 top
PR657  -  [R0402_0OHM]  45.77 135.56 0 top
PR659  -  [R_0402]  27.8 146.55 0 top
PR680  -  [R_0805]  102.25 135.28 270 bottom
PR681  -  [R0402_0OHM]  107.49 134.42 0 top
PR683  -  [R_0402]  107.24 129.21 0 bottom
PR684  -  [R_0402]  109.03 128.37 90 bottom
PR687  -  [R_0402]  97.55 123.37 180 bottom
PR688  -  [R0402_0OHM]  104.26 121.47 0 bottom
PR689  -  [R_0402]  97.6 122.43 270 bottom
PR691  -  [R_0402]  20.7 144.25 270 top
PR692  -  [R_0402]  102.41 120.51 0 bottom
PR697  -  [R_0402]  102.41 121.47 0 bottom
PR700  -  [R0402_0OHM]  24.56 177.16 0 top
PR701  -  [R_1206_4P-D]  30.51 171.82 180 top
PR702  -  [R0402_0OHM]  34.3 164.9 180 top
PR703  -  [R_0402]  53.23 168.65 180 bottom
PR704  -  [R0402_0OHM]  52.33 167.74 90 top
PR705  -  [R0402_0OHM]  53.21 167.74 90 top
PR706  -  [R_0402]  145.61 166.82 270 top
PR707  -  [R_0402]  145.61 165.04 270 top
PR709  -  [R0402_0OHM]  145.8 163.25 0 top
PR710  -  [R0402_0OHM]  47.25 165.9 0 bottom
PR713  -  [R_0402]  48.15 164.71 180 bottom
PR714  -  [R_0402]  49.52 164.71 0 bottom
PR715  -  [R_0603]  55.56 163.63 0 top
PR716  -  [R_1206_4P-D]  88.67 156.2 180 bottom
PR717  -  [R0402_0OHM]  50.42 167.77 270 top
PR718  -  [R0402_0OHM]  51.63 159.07 270 top
PR719  -  [R0402_0OHM]  50.74 159.07 270 top
PR720  -  [R_0402]  47.36 161.47 0 top
PR721  -  [R_1206]  61.79 153.91 0 top
PR722  -  [R_0402]  49.85 159.07 270 top
PR723  -  [R_0402]  231.8 141.56 270 top
PR724  -  [R0402_0OHM]  234.2 141.72 180 top
PR725  -  [R_0402]  231.08 143.31 0 top
PR726  -  [R_0402]  226.95 139.49 90 top
PR727  -  [R_0402]  231.99 142.43 180 top
PR728  -  [R_0402]  231.99 144.2 180 top
PR730  -  [R_0402]  227.9 140.4 270 top
PR731  -  [R_0402]  228.86 140.4 270 top
PR732  -  [R_0402]  224.86 148.28 270 top
PR733  -  [R_0402]  220.59 143.94 0 top
PR734  -  [R_0402]  220.59 147.88 0 top
PR735  -  [R_0402]  220.59 142.99 0 top
PR736  -  [R_0402]  51.45 168.65 180 bottom
PR737  -  [R0402_0OHM]  221.5 146.93 180 top
PR738  -  [R_0402]  223.97 147.36 90 top
PR739  -  [R_0402]  221.5 144.9 180 top
PR740  -  [R_0402]  221.5 142.1 180 top
PR741  -  [R_0402]  48.63 167.69 0 top
PR742  -  [R_1206]  55.06 168.96 270 bottom
PR743  -  [R_0402]  49.52 165.6 0 bottom
PR744  -  [R_0402]  50.53 167.76 0 bottom
PR745  -  [R0402_0OHM]  220.52 140.19 0 top
PR746  -  [R_0402]  47.36 162.36 0 top
PR747  -  [R_0402]  47.36 160.58 0 top
PR748  -  [R_0402]  234.62 138.1 0 top
PR801  -  [R_0402]  233.75 80.69 90 top
PR802  -  [R_0402]  166.99 72.23 0 top
PR804  -  [R_0402]  174.16 74.37 0 top
PR807  -  [R_0402]  230.65 78.29 180 top
PR808  -  [R_0402]  171.2 74.3 270 top
PR810  -  [R_0402]  227.06 88.64 0 top
PR811  -  [R0402_0OHM]  43.88 150.5 270 top
PR812  -  [R0402_0OHM]  228.79 83.82 270 top
PR813  -  [R_0402]  108.97 155.68 90 top
PR814  -  [R_0402]  156.15 159.24 90 top
PR815  -  [R_0402]  109.92 155.68 90 top
PR816  -  [R_0402]  114.62 151.93 90 top
PR817  -  [R_0402]  74.69 151.73 180 top
PR818  -  [R_0402]  101.8 161.72 180 top
PR819  -  [R_0402]  192.91 49.6 270 top
PR821  -  [R_0603]  71.44 152.29 270 top
PR822  -  [R_0402]  101.8 160.84 180 top
PR823  -  [R_0402]  183.96 45.57 90 top
PR824  -  [R_0402]  181.47 48.06 0 top
PR826  -  [R_0402]  184.91 35.63 270 top
PR827  -  [R_0402]  184.91 36.49 90 top
PR828  -  [R_0402]  173.88 25.12 270 top
PR829  -  [R_0402]  192.05 39.19 270 top
PR830  -  [R_0402]  166.59 25.97 0 top
PR831  -  [R0805_0OHM]  33.38 141.6 0 top
PR832  -  [R0402_0OHM]  35.26 142.93 180 top
PR833  -  [R_0402]  174.22 16.97 180 top
PR834  -  [R_0402]  175.11 17.88 270 top
PR835  -  [R_0805]  32.68 138.61 0 top
PR838  -  [R0402_0OHM]  35.57 144.52 180 top
PR839  -  [R_0402]  185.1 42.07 270 top
PR840  -  [R_0402]  185.1 42.93 90 top
PR843  -  [R0402_0OHM]  37.85 147.3 90 top
PR844  -  [R_0402]  170.6 21.68 90 top
PR846  -  [R_0402]  40.53 134.23 180 top
PR847  -  [R0402_0OHM]  38.29 136.18 90 top
PR849  -  [R_0402]  192.06 40.77 90 top
PR850  -  [R0402_0OHM]  38.74 147.3 90 top
PR854  -  [R0805_0OHM]  40.01 135.28 90 top
PR857  -  [R0402_0OHM]  40.96 147.3 90 top
PR858  -  [R_0402]  40.07 148.21 270 top
PR862  -  [R0402_0OHM]  42.75 136.59 90 top
PR863  -  [R_0402]  41.85 147.3 90 top
PR864  -  [R_0402]  195.4 83.18 180 top
PR866  -  [R0402_0OHM]  43.88 147.3 90 top
PR868  -  [R0402_0OHM]  42.74 147.3 90 top
PR869  -  [R_0402]  218.44 95.57 270 top
PR870  -  [R_0402]  219.39 94.66 90 top
PR874  -  [R_0402]  42.74 149.58 90 top
PR875  -  [R_0402]  222.07 91.94 180 top
PR877  -  [R0805_0OHM]  47.56 140.03 270 top
PR881  -  [R_0402]  184.42 49.85 90 top
PR882  -  [R0402_0OHM]  178.61 48.69 0 top
PR883  -  [R_0402]  221.95 96.51 180 top
PR884  -  [R_0402]  190.26 38.28 90 top
PR885  -  [R_0402]  190.26 41.68 270 top
PR886  -  [R0402_0OHM]  191.15 38.28 90 top
PR887  -  [R0402_0OHM]  191.17 41.68 270 top
PR890  -  [R0402_0OHM]  113.03 155.23 90 top
PR894  -  [R_0402]  165.56 22.29 90 top
PR895  -  [R0402_0OHM]  165.56 25.15 270 top
PRP2  -  [RP_0804_8P4R]  72.91 162.23 90 top
PU1  -  [TS5A63157DCKR_SC70-6]  222.58 123.35 180 top
PU100  -  [TPS51225CRUKR_QFN20_3X3]  196.7 38.89 270 top
PU200  -  [RT8207MZQW_WQFN20_3X3]  175.92 85.04 0 top
PU300  -  [TPS51212DSCR_SON10_3X3]  177.69 94.68 90 top
PU400  -  [SY8033BDBC_DFN10_3X3]  200.26 56.11 270 top
PU500  -  [ISL95812HRZ-T_QFN32_4X4]  123.7 145.73 0 bottom
PU600  -  [ISL62883CHRTZ-T_TQFN40_5X5]  21.38 146.23 0 top
PU602  -  [SY8036DBC_DFN10_3X3]  106.44 134.19 0 bottom
PU603  -  [G971ADJF11U_SO8]  99.14 122.93 90 bottom
PU700  -  [BQ24738RGRR_QFN20_3P5X3P5]  52.5 165.04 180 top
PU701  -  [LM393DR_SO8]  228.96 142.04 90 top
PU703  -  [INA199A2DCKR_SC70-6]  46.84 167.23 90 bottom
PU704  -  [TC7SH08FU_SSOP5]  235.27 139.36 90 top
PU800  -  [CD3301RHHR_QFN36_6X6]  38.32 139.33 0 top
PU801  -  [TC7SH08FU_SSOP5]  225.05 86.68 270 top
PU804  -  [TC7SH08FU_SSOP5]  230.26 83.76 270 top
PU805  -  [TC7SH08FU_SSOP5]  191.79 50.72 180 top
PU806  -  [TC7SH08FU_SSOP5]  190.96 47.49 180 top
PU807  -  [TC7SH08FU_SSOP5]  180.98 46.93 270 top
PU808  -  [TC7SH08FU_SSOP5]  177.72 18.87 90 top
Q1  -  [PMST3904_SOT323-3]  118.71 92.45 270 bottom
Q2  -  [PMST3904_SOT323-3]  27.77 140.29 90 top
Q3  -  [PMST3904_SOT323-3]  136.81 121.02 270 bottom
Q4  -  [PMST3904_SOT323-3]  217.87 85.81 180 top
Q21  -  [FDC654P-G_SSOT-6]  214.54 167.23 270 top
Q22  -  [L2N7002WT1G_SC-70-3]  212.85 164.84 270 top
Q23  -  [DMG2301U-7_SOT23-3]  232.41 166.91 180 bottom
Q24  -  [L2N7002WT1G_SC-70-3]  190.88 148.83 90 bottom
Q29  -  [DMN66D0LDW-7_SOT363-6]  80.78 36.26 270 top
Q32  -  [PMV65XP_SOT23-3]  190.22 145.6 90 bottom
Q45  -  [L2N7002WT1G_SC-70-3]  221.17 80.7 180 top
Q47  -  [L2N7002WT1G_SC-70-3]  203.46 90.54 90 top
Q48  -  [L2N7002WT1G_SC-70-3]  279.4 183.25 270 top
Q52  -  [DMN66D0LDW-7_SOT363-6]  155.5 112.9 0 top
Q59  -  [L2N7002WT1G_SC-70-3]  274.64 176.33 180 top
Q63  -  [AO4354_SOIC-8]  162.05 113.38 180 top
Q70  -  [L2N7002WT1G_SC-70-3]  157.42 116.64 270 top
Q71  -  [L2N7002WT1G_SC-70-3]  144.09 41.84 90 top
Q72  -  [L2N7002WT1G_SC-70-3]  157.11 28.01 90 top
Q74  -  [DMN66D0LDW-7_SOT363-6]  225.43 110.37 270 top
Q75  -  [PDTA114EU_SC70-3]  230.14 109.72 270 top
Q76  -  [DMN66D0LDW-7_SOT363-6]  170.9 54.28 180 top
Q77  -  [L2N7002WT1G_SC-70-3]  277.56 180.07 0 top
Q79  -  [PDTA114EU_SC70-3]  225.34 106.31 90 top
Q81  -  [PDTA114EU_SC70-3]  221.98 111.65 180 top
Q83  -  [DMN66D0LDW-7_SOT363-6]  225.05 163.93 90 bottom
Q84  -  [DMN66D0LDW-7_SOT363-6]  223.71 113.06 270 top
Q89  -  [L2N7002WT1G_SC-70-3]  214.44 144.2 180 top
Q100  -  [L2N7002WT1G_SC-70-3]  228.39 106.21 90 top
Q106  -  [DMN66D0LDW-7_SOT363-6]  286.58 151.23 90 bottom
Q123  -  [DMN66D0LDW-7_SOT363-6]  165.49 54.74 270 top
Q124  -  [DMN66D0LDW-7_SOT363-6]  212.34 145.64 90 top
Q324  -  [L2N7002WT1G_SC-70-3]  277.82 151.06 270 bottom
Q325  -  [DMN66D0LDW-7_SOT363-6]  257.43 177.17 270 top
Q326  -  [L2N7002WT1G_SC-70-3]  258.38 180.39 0 top
Q330  -  [DMN66D0LDW-7_SOT363-6]  282.83 152.25 90 top
Q331  -  [DMN66D0LDW-7_SOT363-6]  174.69 160.76 90 top
QC1  -  [L2N7002WT1G_SC-70-3]  102.94 53.27 180 top
QC3  -  [L2N7002WT1G_SC-70-3]  136.21 114.36 180 top
QC5  -  [L2N7002WT1G_SC-70-3]  107.32 50.6 0 top
QD6  -  [DMN66D0LDW-7_SOT363-6]  91.38 25.91 270 top
QD7  -  [L2N7002WT1G_SC-70-3]  100.33 22.02 270 top
QD9  -  [L2N7002WT1G_SC-70-3]  98.3 27.61 0 top
QH2  -  [BSS138W-7-F_SOT323-3]  156.02 122.68 180 top
QH3  -  [L2N7002WT1G_SC-70-3]  165.61 117.15 0 top
QH4  -  [DMN66D0LDW-7_SOT363-6]  176.28 116.27 270 top
QV1  -  [AO4354_SOIC-8]  86.07 91.37 270 top
QV2  -  [L2N7002WT1G_SC-70-3]  93.1 93.08 90 top
QV3  -  [PMST3904_SOT323-3]  94.04 121.28 90 top
QV4  -  [MMBT3906WT1G_SC70-3]  90.82 120.01 180 top
QV5  -  [L2N7002WT1G_SC-70-3]  97.22 95.62 90 top
QV6  -  [L2N7002WT1G_SC-70-3]  97.22 93.08 90 top
QV7  -  [PMST3904_SOT323-3]  91.1 115.24 270 top
QV8  -  [PMST3904_SOT323-3]  58.26 148.64 90 top
QV11  -  [L2N7002WT1G_SC-70-3]  81.79 90.67 270 top
QV12  -  [DMG2301U-7_SOT23-3]  93.13 114.73 270 top
R5  -  [R0402_0OHM]  284.8 161.71 90 top
R6  -  [R0402_0OHM]  272.35 153.84 90 bottom
R7  -  [R_0402]  238.65 128.13 180 top
R15  -  [R0402_0OHM]  293.82 166.92 90 bottom
R30  -  [R_0402]  56.66 90.48 180 bottom
R38  -  [R_0402]  56.66 89.59 180 bottom
R39  -  [R_0402]  266.27 154.87 180 top
R40  -  [R0402_0OHM]  281.24 155.64 270 top
R51  -  [R_0402]  218.71 84.7 180 top
R52  -  [R_0402]  206.69 70.81 270 top
R55  -  [R_0402]  217.54 88.76 0 top
R61  -  [R_0402]  136.78 153.36 270 top
R62  -  [R_0402]  24.32 205.53 90 top
R63  -  [R_0402]  23.43 205.53 90 top
R64  -  [R_0402]  12.77 205.53 90 top
R65  -  [R_0402]  25.99 197.16 180 top
R68  -  [R_0402]  13.66 205.53 90 top
R69  -  [R_0402]  13.07 201.48 0 top
R70  -  [R_0402]  13.07 200.59 0 top
R71  -  [R_0402]  16.32 205.53 90 top
R72  -  [R_0402]  20.21 202.49 180 bottom
R73  -  [R_0402]  25.72 206.04 90 bottom
R74  -  [R_0402]  17.21 205.53 90 top
R75  -  [R_0402]  17.47 197.21 90 bottom
R76  -  [R_0402]  22.72 200.84 0 top
R77  -  [R_0402]  19.88 205.53 90 top
R78  -  [R_0402]  20.77 205.53 90 top
R79  -  [R_0402]  25.99 198.05 180 top
R80  -  [R_0402]  25.99 199.89 180 top
R81  -  [R_0402]  22.72 198.05 0 top
R82  -  [R_0402]  22.72 199.89 0 top
R85  -  [R_0402]  11.75 198.8 90 top
R86  -  [R_0402]  25.99 199 180 top
R87  -  [R_0402]  13.99 199.7 180 top
R88  -  [R_0402]  22.72 199 0 top
R100  -  [R_0402]  195.89 165.66 0 top
R101  -  [R_0402]  194.93 157.66 0 top
R104  -  [R0402_0OHM]  199.96 155.13 270 top
R105  -  [R_0402]  197.49 167.49 90 top
R106  -  [R_0402]  195.7 167.19 0 top
R107  -  [R_0402]  198.69 168.13 90 top
R108  -  [R_0402]  199.58 169.04 270 top
R114  -  [R_0402]  204.54 157.52 90 top
R152  -  [R0402_0OHM]  245.95 162.93 180 top
R153  -  [R_0402]  274.77 179.36 90 top
R154  -  [R0603_0OHM]  247.78 159.38 0 top
R159  -  [R_0402]  204.85 172.56 180 bottom
R160  -  [R_0402]  202.2 172.56 0 bottom
R392  -  [R_0402]  198.77 78.35 180 top
R407  -  [R_0402]  217.79 71.36 0 top
R415  -  [R_0402]  173.24 159.69 180 top
R416  -  [R_0402]  174.11 159.69 0 top
R418  -  [R_0402]  206.69 68.39 270 top
R420  -  [R_0402]  207.71 69.89 90 top
R422  -  [R_0402]  216.42 164.2 180 top
R423  -  [R_0402]  214.57 164.21 270 top
R424  -  [R_0402]  220.33 78.1 0 top
R427  -  [R_0402]  229.24 165.32 270 bottom
R428  -  [R_0402]  230.25 165.32 270 bottom
R429  -  [R0402_0OHM]  209.62 155.9 270 top
R431  -  [R_0402]  194.2 145.97 90 bottom
R432  -  [R_0402]  190.52 137.52 90 bottom
R433  -  [R_0402]  191.4 137.52 90 bottom
R491  -  [R_0402]  180.29 161.41 180 top
R492  -  [R_0402]  171.46 160.58 180 top
R501  -  [R_0402]  88.22 48.06 180 top
R502  -  [R_0402]  85.16 47.16 90 top
R503  -  [R_0402]  85.42 57.52 180 top
R506  -  [R_0402]  78.86 34.92 0 top
R508  -  [R_0402]  84.53 36.38 180 top
R512  -  [R_0402]  174.37 39.69 270 top
R515  -  [R_0402]  164.15 54.14 90 top
R517  -  [R_0402]  172.02 52.36 90 top
R545  -  [R_0402]  234.49 162.68 0 top
R546  -  [R_0402]  234.49 161.79 0 top
R549  -  [R_0402]  245.95 160.07 180 top
R551  -  [R0402_0OHM]  234.49 165.79 0 top
R552  -  [R0402_0OHM]  234.49 163.57 0 top
R553  -  [R_0402]  245.95 157.41 180 top
R555  -  [R0402_0OHM]  245.95 161.85 180 top
R557  -  [R_0402]  245.04 160.96 0 top
R558  -  [R_0402]  245.95 159.18 180 top
R561  -  [R_0402]  235.41 164.9 180 top
R562  -  [R_0402]  245.04 166.66 0 top
R566  -  [R_0402]  246.88 158.3 0 top
R571  -  [R_0402]  249.35 198.71 0 bottom
R572  -  [R_0402]  249.35 191.09 0 bottom
R573  -  [R_0402]  249.35 197.82 0 bottom
R574  -  [R_0402]  249.35 190.2 0 bottom
R575  -  [R0402_0OHM]  263.46 187.63 180 top
R576  -  [R0402_0OHM]  263.46 188.52 180 top
R577  -  [R0402_0OHM]  263.46 192.7 180 top
R578  -  [R0402_0OHM]  263.46 193.67 180 top
R585  -  [R_0402]  47.31 97.98 270 top
R589  -  [R_0402]  48.2 97.98 270 top
R657  -  [R_0402]  212.28 115.99 90 top
R676  -  [R_0402]  185.61 31.85 90 top
R677  -  [R_0402]  180.58 28.43 0 top
R693  -  [R_0402]  202.12 146.5 90 bottom
R694  -  [R_0402]  210.86 149.28 180 top
R695  -  [R_0402]  216.1 153.28 180 top
R703  -  [R0402_0OHM]  203.01 146.5 90 bottom
R704  -  [R0402_0OHM]  269.43 190.69 90 bottom
R706  -  [R_0402]  196.8 146.49 90 bottom
R707  -  [R0402_0OHM]  216.35 159.9 90 bottom
R717  -  [R0402_0OHM]  235.65 67.88 270 top
R719  -  [R_0402]  277.26 177.03 180 top
R725  -  [R_0402]  209.08 149.28 180 top
R726  -  [R_0402]  264.86 174.06 270 top
R731  -  [R_0402]  222.37 31.99 0 top
R732  -  [R_0402]  222.37 30.79 0 top
R733  -  [R_0402]  265.75 174.06 270 top
R734  -  [R_0402]  236.67 67.88 270 top
R736  -  [R_0402]  274.96 187.18 90 top
R738  -  [R0402_0OHM]  193.54 68.82 0 top
R740  -  [R_0402]  273.94 187.18 90 top
R755  -  [R_0402]  155.93 154.56 0 bottom
R757  -  [R_0402]  127.95 161.74 270 top
R758  -  [R_0402]  128.34 169.87 270 top
R772  -  [R_0402]  183.83 58.46 90 top
R793  -  [R_0402]  193.54 67.55 0 top
R796  -  [R_0402]  177.01 64.29 0 top
R800  -  [R_0402]  183.83 57.09 270 top
R802  -  [R0402_0OHM]  192.53 76.77 270 top
R803  -  [R_0402]  184.85 56.17 90 top
R804  -  [R_0402]  190.5 75.86 90 top
R806  -  [R_0402]  193.54 63.87 0 top
R807  -  [R_0402]  181.93 58.46 90 top
R811  -  [R_0402]  203.65 70.81 270 top
R812  -  [R_0402]  205.68 87.82 270 top
R816  -  [R_0402]  283.4 190.76 270 top
R817  -  [R_0402]  218.71 73.4 180 top
R825  -  [R_0402]  203.65 67.48 90 top
R830  -  [R0402_0OHM]  200.92 67.35 90 top
R834  -  [R0402_0OHM]  218.71 76.32 180 top
R836  -  [R_0402]  197.85 83.43 0 top
R839  -  [R0402_0OHM]  200.52 80.38 0 top
R843  -  [R_0402]  211.77 86.91 90 top
R850  -  [R_0402]  235.19 77.9 0 top
R853  -  [R0402_0OHM]  236.92 75.29 90 top
R864  -  [R_0402]  235.45 70.86 0 top
R866  -  [R0402_0OHM]  201.44 85.97 180 top
R871  -  [R_0402]  208.6 69.89 90 top
R872  -  [R_0402]  197.85 74.29 0 top
R874  -  [R_0402]  198.77 77.33 180 top
R875  -  [R_0402]  210.57 68.39 270 top
R879  -  [R_0402]  197.85 75.3 0 top
R884  -  [R_0402]  205.68 66.11 270 top
R887  -  [R_0402]  201.44 81.36 180 top
R888  -  [R_0402]  210.38 70.81 270 top
R894  -  [R_0402]  184.6 19.04 90 top
R901  -  [R_0402]  226.07 124.83 180 top
R902  -  [R_0402]  187.51 119.82 0 top
R903  -  [R_0402]  190.2 119.82 180 top
R909  -  [R_0402]  154.5 114.87 270 top
R925  -  [R_0402]  158.74 114.95 180 top
R926  -  [R_0402]  142.04 42.66 0 top
R927  -  [R_0603]  155.72 25.97 0 top
R930  -  [R_0402]  156.96 111.04 90 top
R931  -  [R_0402]  162.99 115.05 0 top
R932  -  [R_0402]  222.68 106.04 180 top
R934  -  [R_0402]  229.94 107.95 0 top
R936  -  [R_0402]  238.65 121.02 180 top
R937  -  [R_0402]  231.48 105.65 90 top
R938  -  [R_0402]  222.65 110.61 180 top
R949  -  [R_0402]  223.6 164.9 180 bottom
R951  -  [R_0402]  227 162.85 180 bottom
R952  -  [R_0402]  201.73 86.91 90 top
R953  -  [R_0402]  226.06 166.35 90 bottom
R955  -  [R_0402]  223.64 114.15 0 top
R957  -  [R_0402]  272.11 193.4 270 top
R958  -  [R_0402]  226.95 166.35 90 bottom
R1068  -  [R0402_0OHM]  201.44 75.17 180 top
R1069  -  [R_0402]  217.79 80.51 0 top
R1070  -  [R0402_0OHM]  200.24 70.92 180 top
R1076  -  [R_0402]  265.7 156.84 180 top
R1079  -  [R_0402]  288.09 150.17 0 bottom
R1080  -  [R_0402]  286.84 150.17 180 bottom
R1081  -  [R_0402]  273.99 158.11 0 bottom
R1082  -  [R_0402]  273.99 159.88 0 bottom
R1086  -  [R_0402]  270.24 150.55 0 top
R1088  -  [R_0402]  283.91 156.91 270 top
R1095  -  [R0805_0OHM]  266.85 166.21 270 top
R1096  -  [R_0402]  265.48 155.88 0 top
R1097  -  [R_0402]  266.78 150.23 180 top
R1099  -  [R_0402]  264.66 164.39 0 top
R1100  -  [R_0402]  273.99 158.99 0 bottom
R1119  -  [R_0402]  263.54 151.12 180 top
R1120  -  [R_0402]  263.54 153.79 180 top
R1137  -  [R_0402]  209.62 154.12 270 top
R1138  -  [R_0402]  217.67 160.61 270 top
R1139  -  [R_0402]  217.18 156.26 180 top
R1141  -  [R_0402]  263.54 152.9 180 top
R1142  -  [R_0402]  263.54 152.01 180 top
R1144  -  [R0402_0OHM]  245.95 164.71 180 top
R1145  -  [R_0402]  283.29 154.55 180 top
R1146  -  [R_0402]  283.03 158.3 180 top
R1154  -  [R_0402]  194.45 64.89 180 top
R1161  -  [R0603_0OHM]  188.22 98.3 90 top
R1162  -  [R_0603]  189.42 98.3 90 top
R1166  -  [R_0402]  243.89 203.95 0 bottom
R1167  -  [R_0402]  260.22 203.37 90 top
R1169  -  [R0402_0OHM]  218.12 103.8 90 top
R1171  -  [R_0402]  212.98 87.82 270 top
R1179  -  [R_0402]  203.65 87.82 270 top
R1180  -  [R0402_0OHM]  204.66 86.91 90 top
R1187  -  [R0402_0OHM]  245.95 156.52 180 top
R1603  -  [R_0402]  280.04 188.7 90 top
R1604  -  [R_0402]  278.07 188.38 90 top
R1605  -  [R_0402]  277.05 188.38 90 top
R1606  -  [R_0402]  279.02 188.7 90 top
R1607  -  [R0402_0OHM]  231.08 67.29 90 top
R1611  -  [R_0402]  156.06 111.94 180 top
R1614  -  [R_0402]  272.35 184.98 270 top
R1620  -  [R_0402]  230.19 67.29 90 top
R1622  -  [R_0402]  175.28 117.72 180 top
R1623  -  [R_0402]  175.28 118.61 180 top
R1624  -  [R_0402]  180.23 117.02 180 top
R1626  -  [R0402_0OHM]  275.66 179.36 90 top
R1629  -  [R_0402]  172.02 114.09 90 top
R1630  -  [R_0402]  177.47 119.69 0 top
R1635  -  [R_0402]  80.89 46.03 0 top
R1636  -  [R_0402]  181.17 118.3 270 top
R1640  -  [R_0402]  41.72 97.07 90 top
R1642  -  [R_0402]  275.08 151.89 270 top
R1653  -  [R_0402]  259.34 203.37 90 top
R1654  -  [R_0402]  265.29 152.01 0 top
R1658  -  [R0603_0OHM]  280.35 161.22 90 top
R1667  -  [R_0402]  217.24 103.8 90 top
R1668  -  [R_0402]  265.29 151.12 0 top
R1672  -  [R0402_0OHM]  135.76 165.42 270 top
R1673  -  [R0402_0OHM]  136.91 165.42 270 top
R1676  -  [R_0402]  285.93 153.53 0 bottom
R1677  -  [R_0402]  282.21 159.57 180 top
R1679  -  [R_0402]  283.4 151.36 90 bottom
R1700  -  [R_0402]  185.49 19.04 90 top
R1702  -  [R_0402]  191.5 23.99 0 top
R1703  -  [R_0402]  267.64 150.23 0 top
R3664  -  [R_0402]  238.65 131.31 180 top
R3665  -  [R_0402]  238.65 124.45 180 top
R3666  -  [R_0402]  225.16 122.29 0 top
R3668  -  [R_0402]  225.16 130.04 0 top
R3669  -  [R_0402]  226.07 129.15 180 top
R3671  -  [R_0402]  225.34 107.94 0 top
R3689  -  [R_0402]  281.85 184.37 45 top
R3690  -  [R_0402]  282.57 183.65 45 top
R3691  -  [R_0402]  285.43 189.27 90 top
R3696  -  [R_0402]  284.55 189.27 90 top
R3697  -  [R_0402]  287.34 191.57 90 top
R3698  -  [R_0402]  286.45 191.57 90 top
R3710  -  [R_0402]  281.04 175.69 0 top
R3711  -  [R_0402]  281.04 176.58 0 top
R3721  -  [R_0402]  282.18 173.66 0 top
R3722  -  [R_0402]  282.18 174.81 0 top
R3727  -  [R_0402]  282.18 171.63 0 top
R3728  -  [R_0402]  282.18 172.77 0 top
R3731  -  [R0402_0OHM]  283.83 153.66 0 top
R3732  -  [R0402_0OHM]  283.9 158.3 0 top
R3735  -  [R0603_0OHM]  189.49 118.86 270 top
R3736  -  [R0603_0OHM]  188.22 118.86 270 top
R3737  -  [R_0402]  193.55 172.66 270 top
R3761  -  [R_0402]  154.05 157.8 270 bottom
R3762  -  [R0603_0OHM]  214.7 164.01 180 bottom
R3763  -  [R0603_0OHM]  244.86 173.35 90 top
R3764  -  [R0603_0OHM]  246.32 173.35 90 top
R3765  -  [R0603_0OHM]  247.78 173.35 90 top
R3766  -  [R0603_0OHM]  249.24 173.35 90 top
R3767  -  [R0603_0OHM]  250.7 173.35 90 top
R3768  -  [R0603_0OHM]  252.16 173.35 90 top
R3769  -  [R0603_0OHM]  253.62 173.35 90 top
R3770  -  [R0603_0OHM]  255.08 173.35 90 top
R3771  -  [R_0402]  219.04 103.8 90 top
R3772  -  [R0402_0OHM]  199.54 91.61 180 top
R3773  -  [R_0402]  167.96 119.79 0 top
R3881  -  [R0805_0OHM]  205.17 154.22 270 top
R3882  -  [R0805_0OHM]  194.32 166.41 90 top
R3883  -  [R0805_0OHM]  201.69 153.3 90 top
R3884  -  [R_0402]  203.77 30.98 90 top
R3885  -  [R_0402]  201.23 146.5 90 bottom
R3886  -  [R_0402]  218.73 159.9 90 bottom
RC1  -  [R_0402]  138.82 96.22 270 top
RC5  -  [R_0402]  103.06 51.12 270 top
RC6  -  [R_0402]  104.71 55.63 270 top
RC7  -  [R_0402]  103.07 49.33 180 top
RC9  -  [R_0402]  104.7 52.95 0 top
RC10  -  [R0402_0OHM]  105.6 55.63 270 top
RC11  -  [R_0402]  96.98 79.8 180 bottom
RC12  -  [R_0402]  102.17 51.12 270 top
RC13  -  [R_0402]  103.07 48.44 180 top
RC15  -  [R_0402]  104.7 52.06 0 top
RC16  -  [R_0402]  105.61 53.84 180 top
RC20  -  [R_0402]  96.98 76.19 180 bottom
RC21  -  [R_0402]  96.98 77.08 180 bottom
RC22  -  [R_0402]  96.07 78.02 0 bottom
RC23  -  [R_0402]  96.98 80.69 180 bottom
RC24  -  [R_0402]  96.98 78.91 180 bottom
RC27  -  [R_0402]  102.16 112.58 0 bottom
RC28  -  [R_0402]  108.84 112.4 270 top
RC29  -  [R_0402]  107.06 114.18 270 top
